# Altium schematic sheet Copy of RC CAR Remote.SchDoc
size A
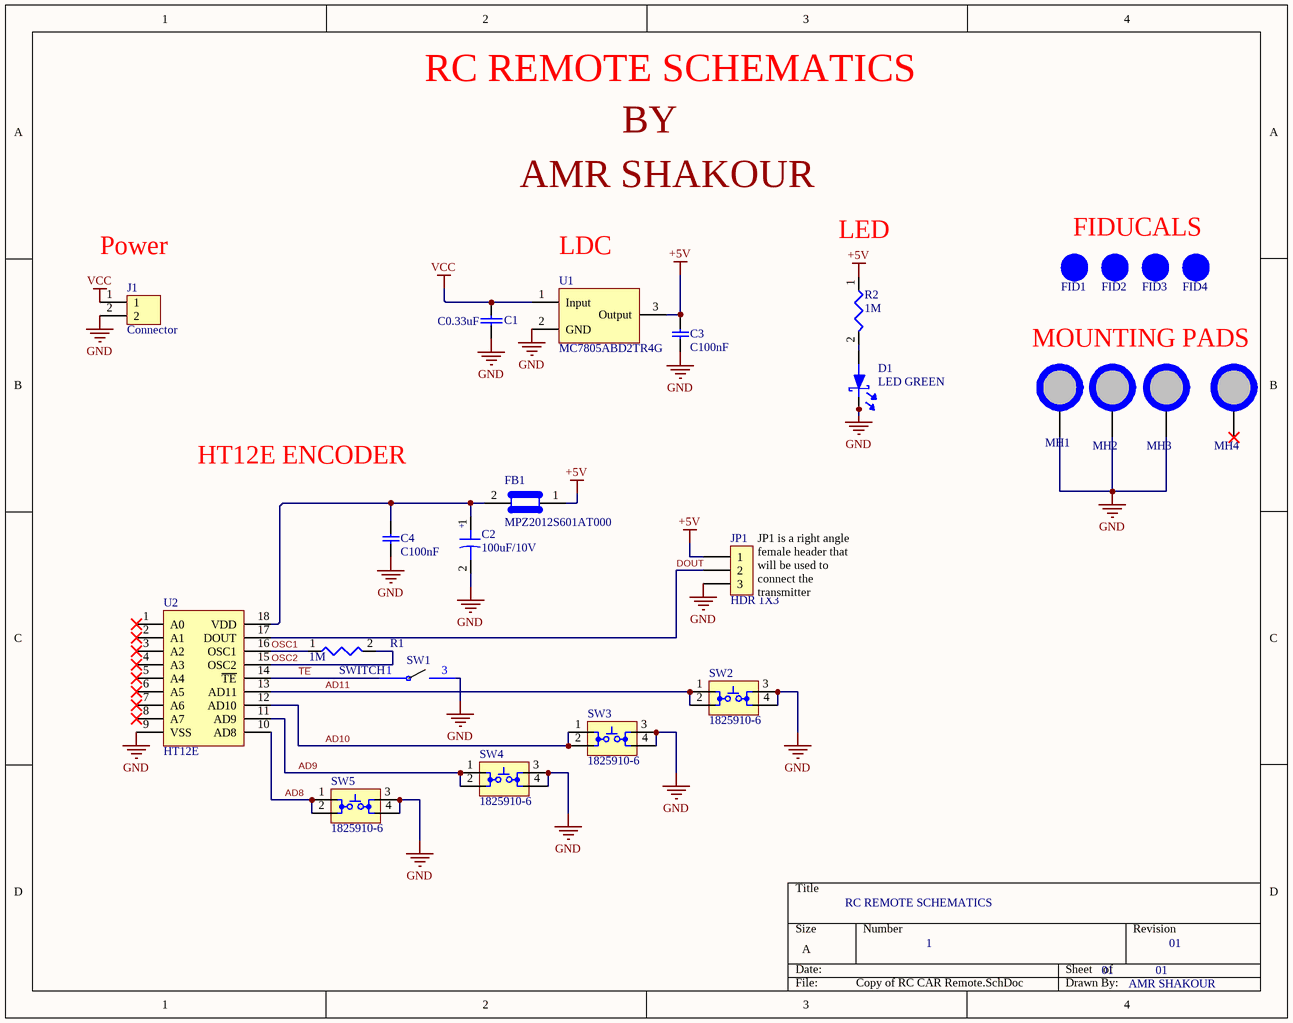
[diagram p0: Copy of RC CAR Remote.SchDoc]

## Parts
C1  C0.33uF  [c0805/95mm]
C2  100uF/10V  [c_alu_c_size]
C3  C100nF  [c0805/95mm]
C4  C100nF  [c0805/95mm]
D1  LED GREEN  [LED 0603]
FB1  MPZ2012S601AT000  [c0805/95mm]
FID1  FID_1MM  [FID_40X120]  (value not drawn)  (no BOM)
FID2  FID_1MM  [FID_40X120]  (value not drawn)  (no BOM)
FID3  FID_1MM  [FID_40X120]  (value not drawn)  (no BOM)
FID4  FID_1MM  [FID_40X120]  (value not drawn)  (no BOM)
J1  Connector  [BM02B]
JP1  HDR 1X3  [HDR 1X3_2.54MM SIDE]
MH1  mh_7.4mmc3.2  [mh_7.4mmc3.2]  (value not drawn)  (no BOM)
MH2  mh_7.4mmc3.2  [mh_7.4mmc3.2]  (value not drawn)  (no BOM)
MH3  mh_7.4mmc3.2  [mh_7.4mmc3.2]  (value not drawn)  (no BOM)
MH4  mh_7.4mmnc3.2  [mh_7.4mmc3.2 NON COPPER NO PLATTED]  (value not drawn)  (no BOM)
R1  1M  [R0805]
R2  1M  [R0805]
SW1  SWITCH  [HDR 1X3_2.54MM Switch]
SW2  1825910-6  [1825910-6]
SW3  1825910-6  [1825910-6]
SW4  1825910-6  [1825910-6]
SW5  1825910-6  [1825910-6]
U1  MC7805ABD2TR4G  [mc7800]
U2  HT12E  [DIP18]

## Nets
+5V: C3.2(100n) FB1.1 JP1.1 R2.1 U1.3(Output)
GND: C1.1 C2.2 C3.1 C4.1 D1.1(Cathode) J1.2 JP1.3 MH1.1 MH2.1 MH3.1 SW1.3 SW2.3 SW2.4 SW3.3 SW3.4 SW4.3 SW4.4 SW5.3 SW5.4 U1.2(GND) U2.9(VSS)
VCC: C1.2(100n) J1.1 U1.1(Input)
AD8: SW5.1 SW5.2 U2.10(AD8)
AD9: SW4.1 SW4.2 U2.11(AD9)
AD10: SW3.1 SW3.2 U2.12(AD10)
AD11: SW2.1 SW2.2 U2.13(AD11)
DOUT: JP1.2 U2.17(DOUT)
OSC1: R1.1 U2.16(OSC1)
OSC2: R1.2 U2.15(OSC2)
~{TE}: SW1.1 U2.14(~{TE})
NetC2_1: C2.1 C4.2(100n) FB1.2 U2.18(VDD)
NetD1_2: D1.2(Anode) R2.2

Not connected (* = marked no-connect by the designer): MH4 1*; U2 1(A0)* 2(A1)* 3(A2)* 4(A3)* 5(A4)* 6(A5)* 7(A6)* 8(A7)*

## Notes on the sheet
- RC REMOTE SCHEMATICS
- BY
- AMR SHAKOUR
- (near J1) Power
- (near U1) LDC
- (near R2) LED
- FIDUCALS
- MOUNTING PADS
- HT12E ENCODER
- (near JP1) JP1 is a right angle female header that will be used to connect the transmitter
- 1
- 01

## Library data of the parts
C1 = C0.33uF 0805: Cap Ceramic 0.33uF 50V X7R 10% SMD 0805 125C Paper T/R C0805C334K5RACAUTO; Manufacturer 1: KEMET; Capacitance: 330nF
C2 = C100uF/10V Ceramic: Cap Aluminum 100uF 10V 20% (5 X 5.4mm) SMD 50mA 1000 hr 85°C T/R  EEE-1AA101WR; Manufacturer 1: Panasonic; Life (Hours): 1000Hour
C3 C4 = C100nF 0805: CAP CER 0.1UF 50V X7R 0805  C2012X7R1H104K085AA; Manufacturer 1: TDK; Dielectric Material: Ceramic; Capacitance: 100nF; Tolerance: 10%
D1 = LED GREEN: LED Uni-Color Green 572nm 2-Pin Chip 0603(1608Metric) T/R  LGL29K-F2J1-24-Z; Manufacturer 1: Osram Opto; Lens Color: White; Forward Current: 20mA; Forward Voltage: 1.7V; Luminous Intensity: 3.5mcd; Viewing Angle: 160°; Lens Style: Flat,Diffused,Colorless,Rectangular; Lens Transparency: Diffused; Test Current: 2mA; Dominant Wavelength: 570nm; Luminous Flux: 0.015lm; Number of LEDs: 1; Lens Size: 0.8mm
FB1 = Ferrite Beads 25% 100MHz 2A 0805: Ferrite Beads Multi-Layer Power 600Ohm 25% 100MHz 2A 100mOhm DCR 0805 T/R MPZ2012S601AT000; Manufacturer 1: TDK; Impedance: 600R; DC Resistance (DCR): 100mR
FID1-FID4 = FID_1MMC: Diducial 40mil diameter, 129mil mask
J1 = BM02B-GHS-TBT(LF)(SN)(N): CONN HEADER SMD 2POS 1.25MM  BM02B-GHS-TBT(LF)(SN)(N); Manufacturer 1: JST; Number of Positions: 2; Connector Type: Outer Shroud Contact; Pitch: 0.049inch
JP1 = HDR 1X3 SIDE: CONN HDR 3POS 0.1 TIN PCB R/A PPTC031LGBN-RC; Manufacturer 1: Sullins; Number of Positions: 3; Connector Type: Header,Socket; Pitch: 0.1inch
MH4 = mh_7.4mmnc3.2: HOLE 7.4MM NON COPPER
R1 R2 = RES SMD 1M OHM 0805: RES SMD 1M OHM 1% 1/8W 0805  RC0805FR-071ML; Manufacturer 1: Yageo Phycomp; Temperature Coefficient: 100ppm/°C; Resistance: 1MR; Power Rating: 125mW; Voltage Rating (DC): 150V
SW1 = switch Toggle: SWITCH TOGGLE SPDT 3A 120V 200MSP3T4B6M2QE; Manufacturer 1: E-Switch; Actuator Material: Brass,Chrome; Voltage Rating (DC): 28V; Illumination Type: Non-Illuminated; Electrical Life: 30000Cycles; Switch Function: On-Off-On; Actuator Type: Standard Round; Actuator Length: 10.41mm
SW2-SW5 = SWITCH: ALCOSWITCH - TE CONNECTIVITY - 1825910-6 - TACT SWITCH, SPST, 0.05A, 24VDC, SOLDER; Manufacturer 1: TE Connectivity Alcoswitch; Actuator Material: PBT; Mechanical Life: 100000Cycles; Operating Force: 160gf; Illumination Type: Non-Illuminated,Illuminated; Switch Travel: 0.25mm; Switch Function: Off-Mom; Actuator Type: Standard; Max Voltage Rating (DC): 24V; Contact Current Rating: 50mA; Contact Resistance: 100mR; Actuator Length: 0.055inch
U1 = MC7805 Regulator: IC REG LINEAR 5V 1A D2PAK; Manufacturer 1: ON Semiconductor; Dropout Voltage: 2V; Number of Outputs: 1; Max Input Voltage: 35V; Polarity: Positive; Output Type: Fixed; Quiescent Current: 6mA; Output Voltage Accuracy: 4%
U2 = HT12E/P: Holtek HT12E/P, Encoder, 2.4  12 V, 18-Pin PDIP; Min Supply Voltage: 2.4V; Max Supply Voltage: 12V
